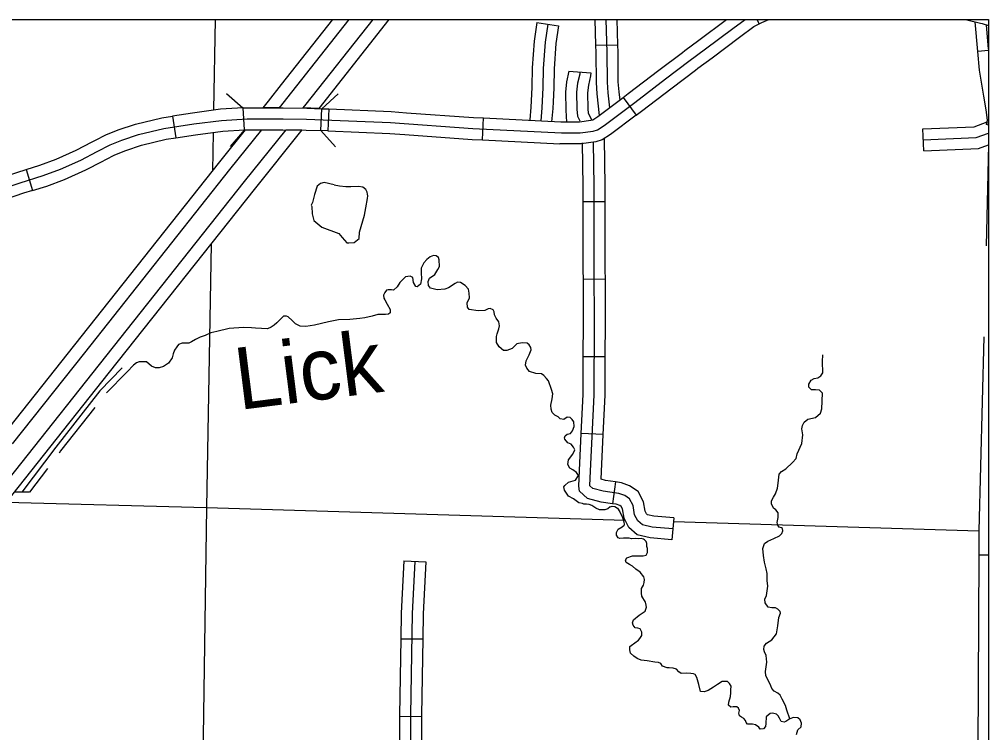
# Model space of a CAD drawing. Extents: x 8749 to 11879, y 13275 to 15339.
# Drawn here: x 10827.5 to 10959.7, y 14359.1 to 14456.3 of the extents above; entities that cross this region are included whole.
import ezdxf

# ---------------------------------------------------------------- set-up
doc = ezdxf.new("R2010")
doc.units = 0
for name, color, linetype in [('Level 19', 7, 'Continuous'), ('Level 31', 7, 'Continuous'), ('Level 32', 7, 'Continuous'), ('Level 35', 7, 'Continuous'), ('Level 38', 7, 'Continuous'), ('Level 4', 7, 'Continuous'), ('Level 43', 7, 'Continuous'), ('Level 45', 7, 'Continuous'), ('Level 5', 7, 'Continuous'), ('R_Draft', 7, 'Continuous')]:
    doc.layers.add(name, color=color, linetype=linetype)

msp = doc.modelspace()

# ---------------------------------------------------------------- linework, layer by layer
at = {"layer": 'Level 19'}
for points in [[(10863.26, 14447.42), (10870.27, 14456.3)], [(10872.44, 14456.3), (10864.6, 14446.37)], [(10866.64, 14444.76), (10875.75, 14456.3)], [(10877.92, 14456.3), (10868.33, 14444.15)], [(10862.95, 14444.27), (10860.77, 14444.26), (10861.5, 14445.17), (10863.26, 14447.42)], [(10864.6, 14446.37), (10862.94, 14444.26)], [(10868.33, 14444.15), (10866.22, 14444.23), (10866.64, 14444.76)], [(10854.85, 14436.88), (10858.35, 14441.25), (10860.54, 14441.26)], [(10860.54, 14441.26), (10856.18, 14435.82)], [(10858.21, 14434.19), (10863.87, 14441.26), (10866.02, 14441.23)], [(10866.02, 14441.23), (10859.54, 14433.13)], [(10835.05, 14411.92), (10854.85, 14436.88)], [(10856.18, 14435.82), (10836.38, 14410.86)], [(10838.41, 14409.25), (10858.21, 14434.19)], [(10859.54, 14433.13), (10839.74, 14408.19)], [(10825.19, 14399.49), (10835.05, 14411.92)], [(10836.38, 14410.86), (10826.52, 14398.43)], [(10828.55, 14396.81), (10838.41, 14409.25)], [(10839.74, 14408.19), (10829.88, 14395.75)], [(10814.02, 14378.49), (10828.55, 14396.81)], [(10829.88, 14395.75), (10815.35, 14377.43)]]:
    msp.add_lwpolyline(points, dxfattribs=at)
at = {"layer": 'Level 31'}
for p, q in [((10928.09, 14456.3), (10928.41, 14455.68)), ((10909.85, 14445.65), (10911.66, 14443.25)), ((10868.75, 14444.13), (10868.75, 14444.13)), ((10869.71, 14444.09), (10869.59, 14441.09)), ((10848.38, 14443.12), (10848.83, 14440.16)), ((10890.66, 14439.86), (10890.8, 14442.86)), ((10890.8, 14442.86), (10890.8, 14442.86)), ((10828.42, 14435.85), (10829.31, 14432.98))]:
    msp.add_line(p, q, dxfattribs=at)
for points in [[(10918.27, 14452.04), (10920.2, 14453.48), (10923.94, 14456.29), (10923.96, 14456.3)], [(10920.06, 14449.63), (10922, 14451.08), (10925.72, 14453.87), (10927.71, 14455.31), (10928.41, 14455.68)], [(10928.41, 14455.68), (10928.77, 14455.86), (10929.75, 14456.3)], [(10956.56, 14456.3), (10958.62, 14455.78)], [(10958.62, 14455.78), (10958.84, 14455.72), (10959.72, 14455.46)], [(10909.85, 14445.65), (10910.55, 14446.18), (10914.73, 14449.38), (10917.94, 14451.79), (10918.27, 14452.04)], [(10911.66, 14443.25), (10912.37, 14443.79), (10916.54, 14446.99), (10919.73, 14449.39), (10920.06, 14449.63)], [(10901.35, 14442.35), (10901.47, 14442.34), (10903.92, 14442.35), (10905.47, 14442.55), (10905.72, 14442.62), (10906.42, 14443.07), (10909.85, 14445.65)], [(10858.01, 14444.23), (10854.94, 14444.04), (10851.1, 14443.54), (10848.38, 14443.12)], [(10858.01, 14444.23), (10859.09, 14444.26)], [(10858.2, 14441.24), (10858.01, 14444.23)], [(10859.09, 14444.26), (10860.86, 14444.26), (10863.48, 14444.26), (10866.71, 14444.22), (10868.75, 14444.13)], [(10868.6, 14441.14), (10868.75, 14444.13)], [(10868.75, 14444.13), (10869.71, 14444.09)], [(10869.71, 14444.09), (10878.21, 14443.73), (10880.3, 14443.58)], [(10837.87, 14439.84), (10839.27, 14440.57), (10840.98, 14441.24), (10843.34, 14442.03), (10846.93, 14442.9), (10848.38, 14443.12)], [(10880.3, 14443.58), (10889.45, 14442.93), (10890.8, 14442.86)], [(10890.8, 14442.86), (10901.35, 14442.35)], [(10911.66, 14443.25), (10908.13, 14440.59), (10906.99, 14439.88), (10906.12, 14439.6), (10904.12, 14439.35), (10901.4, 14439.34), (10901.21, 14439.35)], [(10848.83, 14440.16), (10851.52, 14440.57), (10855.23, 14441.05), (10858.2, 14441.24)], [(10858.2, 14441.24), (10858.6, 14441.26), (10859.09, 14441.26)], [(10859.09, 14441.26), (10860.86, 14441.26), (10863.46, 14441.26), (10866.62, 14441.22), (10868.6, 14441.14)], [(10869.59, 14441.09), (10868.6, 14441.14)], [(10869.59, 14441.09), (10878.04, 14440.73), (10880.09, 14440.59)], [(10828.42, 14435.85), (10830.27, 14436.42), (10832.53, 14437.26), (10835.25, 14438.47), (10837.42, 14439.6), (10837.87, 14439.84)], [(10839.27, 14437.18), (10840.52, 14437.84), (10842, 14438.42), (10844.17, 14439.14), (10847.51, 14439.96), (10848.83, 14440.16)], [(10880.09, 14440.59), (10889.27, 14439.93), (10890.66, 14439.86)], [(10890.66, 14439.86), (10901.21, 14439.35)], [(10829.31, 14432.98), (10831.24, 14433.58), (10833.67, 14434.48), (10836.55, 14435.77), (10838.81, 14436.94), (10839.27, 14437.18)], [(10818.38, 14432.76), (10822.41, 14433.86), (10827.14, 14435.45), (10828.42, 14435.85)], [(10829.31, 14432.98), (10828.07, 14432.6), (10823.29, 14430.99), (10819.17, 14429.86)], [(10881.44, 14382.4), (10881.09, 14375.29), (10880.86, 14361.44), (10880.91, 14354.46), (10880.91, 14345.65)]]:
    msp.add_lwpolyline(points, dxfattribs=at)
at = {"layer": 'Level 32'}
for p, q in [((10906.1, 14452.79), (10909.09, 14452.85)), ((10959.72, 14452.04), (10958.24, 14451.91)), ((10902.47, 14449.24), (10905.45, 14449.02)), ((10950.87, 14438.38), (10950.74, 14441.37)), ((10959.72, 14441.88), (10959.44, 14441.95)), ((10907.39, 14431.44), (10904.39, 14431.42)), ((10907.44, 14420.88), (10904.44, 14420.86)), ((10907.43, 14410.3), (10904.43, 14410.32)), ((10907.13, 14399.69), (10904.14, 14399.83)), ((10908.84, 14393.24), (10908.4, 14390.27)), ((10916.76, 14388.35), (10916.52, 14385.36)), ((10879.94, 14382.48), (10882.94, 14382.33)), ((10879.53, 14371.87), (10882.53, 14371.83)), ((10879.37, 14361.28), (10882.36, 14361.3))]:
    msp.add_line(p, q, dxfattribs=at)
for points in [[(10906.02, 14456.3), (10906.1, 14452.79)], [(10906.35, 14441.25), (10907.27, 14441.83), (10911.46, 14444.99), (10915.64, 14448.19), (10918.84, 14450.59), (10921.1, 14452.28), (10924.83, 14455.08), (10926.52, 14456.3)], [(10907.52, 14456.3), (10907.62, 14451.81), (10907.66, 14447.74), (10907.77, 14446.3), (10908, 14444.26)], [(10909.02, 14456.3), (10909.09, 14452.85)], [(10958.24, 14451.91), (10957.89, 14455.96)], [(10959.72, 14452.25), (10959.43, 14455.54)], [(10906.1, 14452.79), (10906.12, 14451.78), (10906.16, 14447.68), (10906.28, 14446.16), (10906.61, 14443.21)], [(10909.09, 14452.85), (10909.12, 14451.84), (10909.16, 14447.81), (10909.27, 14446.44), (10909.39, 14445.31)], [(10959.44, 14441.95), (10959.58, 14442.57), (10959.4, 14443.95), (10959.05, 14445.84), (10958.46, 14449.38), (10958.24, 14451.91)], [(10902.47, 14449.24), (10902.13, 14447.79), (10901.98, 14446.38), (10902.03, 14443.93), (10902.15, 14442.28)], [(10903.96, 14449.13), (10903.94, 14448.84), (10903.65, 14447.6), (10903.51, 14446.37), (10903.56, 14444.06), (10903.62, 14443.13), (10903.96, 14442.45)], [(10905.45, 14449.02), (10905.42, 14448.61), (10905.13, 14447.35), (10905.02, 14446.31), (10905.06, 14444.13), (10905.1, 14443.53), (10905.58, 14442.58)], [(10811.93, 14429.44), (10822.85, 14432.42), (10827.6, 14434.02), (10830.76, 14435), (10833.1, 14435.87), (10835.9, 14437.12), (10838.12, 14438.27), (10839.89, 14439.21), (10841.49, 14439.83), (10843.76, 14440.59), (10847.22, 14441.43), (10851.31, 14442.05), (10855.08, 14442.54), (10858.55, 14442.76), (10860.86, 14442.76), (10863.47, 14442.76), (10866.66, 14442.72), (10878.12, 14442.23), (10889.36, 14441.43), (10901.43, 14440.84), (10904.02, 14440.85), (10905.79, 14441.07), (10906.35, 14441.25)], [(10950.74, 14441.37), (10957.74, 14441.67), (10959.53, 14442.34), (10959.44, 14441.95)], [(10907.39, 14431.44), (10907.39, 14433.6), (10907.31, 14440.08)], [(10950.8, 14439.87), (10958.04, 14440.19)], [(10958.04, 14440.19), (10959.72, 14440.81)], [(10904.39, 14431.42), (10904.39, 14433.58), (10904.31, 14439.49)], [(10905.32, 14392.73), (10905.31, 14392.77), (10905.4, 14394.73), (10905.89, 14405.12), (10905.97, 14414.96), (10905.93, 14422.17), (10905.89, 14433.59), (10905.81, 14439.51)], [(10950.87, 14438.38), (10958.34, 14438.7), (10959.72, 14439.21)], [(10904.44, 14420.86), (10904.43, 14422.16), (10904.39, 14431.42)], [(10907.44, 14420.88), (10907.43, 14422.17), (10907.39, 14431.44)], [(10904.43, 14410.32), (10904.47, 14414.97), (10904.44, 14420.86)], [(10907.43, 14410.3), (10907.47, 14414.96), (10907.44, 14420.88)], [(10904.14, 14399.83), (10904.39, 14405.16), (10904.43, 14410.32)], [(10907.13, 14399.69), (10907.39, 14405.07), (10907.43, 14410.3)], [(10908.4, 14390.27), (10906.85, 14390.5), (10904.98, 14390.98), (10903.92, 14391.99), (10903.8, 14392.68), (10903.9, 14394.8), (10904.14, 14399.83)], [(10908.84, 14393.24), (10907.44, 14393.44), (10906.85, 14393.6), (10906.9, 14394.66), (10907.13, 14399.69)], [(10916.64, 14386.86), (10913.81, 14387.09), (10912.48, 14387.41), (10911.85, 14387.95), (10911.43, 14388.78), (10911.21, 14390.05), (10910.75, 14390.92), (10910.07, 14391.38), (10909.29, 14391.65), (10907.15, 14391.97), (10905.73, 14392.34), (10905.32, 14392.73)], [(10916.76, 14388.35), (10914.05, 14388.57), (10913.19, 14388.78), (10913.05, 14388.89), (10912.87, 14389.25), (10912.64, 14390.55), (10911.9, 14391.96), (10910.74, 14392.73), (10909.65, 14393.12), (10908.84, 14393.24)], [(10916.52, 14385.36), (10913.57, 14385.6), (10911.78, 14386.03), (10910.64, 14387.01), (10910, 14388.3), (10909.77, 14389.56), (10909.6, 14389.89), (10909.39, 14390.03), (10908.93, 14390.19), (10908.4, 14390.27)], [(10879.94, 14382.48), (10879.59, 14375.34), (10879.53, 14371.87)], [(10882.94, 14382.33), (10882.59, 14375.24), (10882.53, 14371.83)], [(10879.53, 14371.87), (10879.36, 14361.44), (10879.37, 14361.28)], [(10882.53, 14371.83), (10882.36, 14361.43), (10882.36, 14361.3)], [(10879.37, 14361.28), (10879.41, 14354.45), (10879.41, 14350.73)], [(10882.36, 14361.3), (10882.41, 14354.46), (10882.41, 14350.73)]]:
    msp.add_lwpolyline(points, dxfattribs=at)
at = {"layer": 'Level 35'}
for points in [[(10870.42, 14433.76), (10869.06, 14434.06), (10868.58, 14433.91), (10868.13, 14433.56), (10867.78, 14432.45), (10867.48, 14431.34), (10867.3, 14430.99), (10867.38, 14430.79), (10867.45, 14429.8), (10867.65, 14428.89), (10868.74, 14427.96), (10871.08, 14427.1), (10871.51, 14426.55), (10872.19, 14425.84), (10872.46, 14425.84), (10873.15, 14425.89), (10873.85, 14426.42), (10873.88, 14427.31), (10874.56, 14429.6), (10874.76, 14430.61), (10874.98, 14431.9), (10875.03, 14432.25), (10874.98, 14432.48), (10874.96, 14432.75), (10874.78, 14433.11), (10874.35, 14433.41), (10873.78, 14433.51), (10872.72, 14433.46), (10872.04, 14433.46), (10871.18, 14433.58), (10870.42, 14433.71)], [(10886.93, 14420.28), (10886.05, 14419.72), (10885.54, 14419.52), (10884.49, 14419.42), (10883.6, 14419.64), (10883.33, 14420.02), (10883.25, 14420.55), (10883.45, 14421.01), (10884.18, 14421.51), (10884.59, 14422.19), (10884.81, 14422.62), (10884.76, 14423.5), (10884.66, 14423.86), (10884.36, 14424.06), (10884.01, 14424.11), (10883.53, 14423.93), (10883.08, 14423.58), (10882.65, 14423.12)], [(10882.65, 14423.12), (10882.32, 14422.37), (10882.3, 14421.76), (10882.37, 14420.93), (10882.2, 14420.2), (10881.77, 14419.85), (10881.57, 14419.9), (10881.26, 14420.43), (10881.16, 14421.11), (10880.8, 14421.29), (10880.18, 14421.21), (10879.4, 14420.45), (10879.02, 14419.85), (10878.52, 14419.39), (10878.27, 14419.42), (10877.81, 14419.42), (10877.56, 14419.37), (10877.33, 14419.09), (10877.18, 14418.69), (10877.23, 14418.31), (10877.36, 14418.08), (10877.66, 14417.5)], [(10890.98, 14416.62), (10890.08, 14416.57), (10888.87, 14416.74), (10888.64, 14417.07), (10888.57, 14417.65), (10888.9, 14418.33), (10888.85, 14418.99), (10888.77, 14419.52), (10888.32, 14420.02), (10887.69, 14420.45), (10887.26, 14420.48), (10886.93, 14420.28)], [(10877.66, 14417.5), (10878.06, 14416.74), (10878.06, 14416.29), (10877.86, 14416.11), (10877.46, 14416.06), (10876.4, 14416.09), (10875.62, 14415.84), (10874.64, 14415.61), (10873.96, 14415.53), (10872.57, 14415.41), (10871.03, 14415.36), (10869.67, 14415.08), (10867.76, 14414.63)], [(10892.59, 14413.08), (10892.67, 14413.45), (10892.92, 14414.13), (10893, 14414.51), (10892.92, 14415.06), (10892.52, 14415.56), (10892.32, 14416.02), (10892.27, 14416.42), (10892.12, 14416.72), (10891.74, 14416.88), (10891.44, 14416.85), (10890.98, 14416.62)], [(10867.76, 14414.63), (10866.58, 14414.45), (10865.82, 14414.5), (10865.16, 14414.8), (10864.69, 14415.26), (10864.16, 14415.74), (10863.93, 14415.86), (10863.55, 14415.84), (10863.2, 14415.53), (10862.62, 14414.93), (10862.24, 14414.63), (10861.84, 14414.32)], [(10853.6, 14413.57), (10852.85, 14413.22), (10852.17, 14412.97), (10851.52, 14412.64), (10850.99, 14412.34), (10850.63, 14412.16), (10850.23, 14412.14), (10849.7, 14412.16), (10849.2, 14411.96), (10848.97, 14411.66), (10848.64, 14411.21), (10848.47, 14410.7), (10848.34, 14410.17), (10847.86, 14409.44), (10847.16, 14408.99), (10846.55, 14408.79), (10846.07, 14408.79), (10845.52, 14409.01)], [(10861.84, 14414.32), (10861.34, 14414.12), (10860.51, 14414.17), (10859.73, 14414.22), (10859.17, 14414.27), (10858.06, 14414.3), (10856.12, 14414.17), (10854.44, 14413.77), (10853.6, 14413.57)], [(10897.96, 14408.01), (10897.1, 14408.31), (10896.73, 14408.74), (10896.55, 14409.17), (10896.63, 14409.77), (10897.05, 14410.58), (10897.31, 14411.23), (10897.28, 14411.56), (10897.05, 14411.94), (10896.78, 14412.17), (10896.07, 14412.22), (10895.34, 14412.09), (10894.74, 14411.44), (10893.98, 14411.18), (10893.53, 14411.18), (10892.95, 14411.64), (10892.59, 14412.27), (10892.59, 14413.08)], [(10845.52, 14409.01), (10844.84, 14409.61), (10844.23, 14409.61), (10843.83, 14409.63), (10843.47, 14409.5), (10843.07, 14409.16), (10842.19, 14408.25), (10842.14, 14408.2)], [(10937.06, 14405.35), (10936.63, 14405.74), (10936.12, 14405.82), (10935.57, 14405.82), (10935.19, 14406.17), (10935.19, 14406.58), (10935.52, 14407.11), (10935.9, 14407.36), (10936.4, 14407.43), (10936.83, 14407.69), (10937.11, 14408.11), (10937.06, 14409.68), (10937.09, 14410.55)], [(10900, 14403.71), (10900.2, 14404.58), (10900.25, 14405.24), (10900.1, 14405.84), (10899.7, 14407.03), (10899.42, 14407.36), (10899.02, 14407.76), (10898.74, 14407.96), (10897.96, 14408.01)], [(10936.1, 14402.03), (10936.78, 14402.62), (10936.96, 14403.2), (10937.06, 14405.35)], [(10901.76, 14392.57), (10901.89, 14392.77), (10902.39, 14393.2), (10903.35, 14393.47), (10903.75, 14394.13), (10903.48, 14394.51), (10903, 14394.91), (10902.57, 14395.14), (10902.32, 14395.62), (10902.42, 14396.25), (10903.02, 14397.05), (10903.25, 14397.63), (10903.1, 14397.99), (10902.75, 14398.37), (10902.32, 14398.57), (10901.89, 14399.07), (10901.86, 14399.27), (10901.96, 14399.55), (10902.24, 14399.75), (10902.7, 14399.83), (10902.95, 14400.21), (10903.17, 14400.79), (10903.12, 14401.44), (10902.92, 14401.77), (10902.62, 14402.02), (10902.22, 14402.05), (10901.76, 14401.74), (10901.26, 14401.85), (10900.98, 14402.12), (10900.55, 14402.35), (10900.18, 14402.73), (10900.05, 14403.16), (10900, 14403.71)], [(10931.16, 14394.28), (10931.46, 14394.67), (10932.04, 14395.05), (10932.97, 14395.88), (10933.48, 14396.46), (10933.58, 14397.07), (10934.23, 14398.48), (10934.39, 14399.66), (10934.26, 14400.5), (10934.31, 14400.93), (10934.56, 14401.4), (10935.04, 14401.78), (10936.1, 14402.03)], [(10931.46, 14386.99), (10931.14, 14387.09), (10930.98, 14387.34), (10930.86, 14387.7), (10931.01, 14388.4), (10931.03, 14389.01), (10930.68, 14389.46), (10930.38, 14389.66), (10930.1, 14390.26), (10930.1, 14390.67), (10930.38, 14391.15), (10930.66, 14391.6), (10930.91, 14392.39), (10931.03, 14393.07), (10931.16, 14394.28)], [(10908.1, 14389.86), (10907.78, 14389.57), (10907.38, 14389.42), (10907.1, 14389.42), (10906.65, 14389.45), (10906.12, 14389.67), (10905.59, 14390.05), (10905.21, 14390.15), (10904.86, 14390.23), (10904.51, 14390.23), (10904.31, 14390.28), (10903.8, 14390.38), (10903.8, 14390.38), (10903.07, 14390.93), (10902.42, 14391.31), (10902.12, 14391.72), (10901.84, 14392.14), (10901.76, 14392.57)], [(10828.9, 14391.83), (10826.79, 14391.85)], [(10908.1, 14389.86), (10908.36, 14389.95), (10908.71, 14389.9), (10909.08, 14389.66), (10909.41, 14389.17), (10909.79, 14388.39), (10909.97, 14387.8), (10910, 14387.46), (10909.94, 14387.28), (10909.79, 14387.12)], [(10910.69, 14385.58), (10909.9, 14385.57), (10909.4, 14385.54), (10909.17, 14385.62), (10908.97, 14385.97), (10908.94, 14386.35), (10909.2, 14386.8), (10909.75, 14387.11), (10909.79, 14387.12)], [(10928.94, 14384.19), (10929.15, 14384.85), (10929.6, 14385.17), (10930.4, 14385.55), (10931.21, 14385.91), (10931.51, 14386.23), (10931.64, 14386.59), (10931.59, 14386.89), (10931.46, 14386.99)], [(10913.2, 14384.19), (10913.08, 14384.42), (10913.09, 14384.85), (10912.99, 14385.13), (10912.79, 14385.35), (10912.65, 14385.45), (10912.33, 14385.52), (10911.9, 14385.5), (10911.53, 14385.52), (10910.98, 14385.5), (10910.69, 14385.58)], [(10912.9, 14376.83), (10912.42, 14377.69), (10912.35, 14378.06), (10912.37, 14378.7), (10912.62, 14379.17), (10912.75, 14379.53), (10912.77, 14379.96), (10912.67, 14380.31), (10912.19, 14380.96), (10911.61, 14381.37), (10911.16, 14381.75), (10910.71, 14382), (10910.28, 14382.28), (10910.18, 14382.58), (10910.38, 14382.91), (10911.16, 14383.18), (10911.77, 14383.18), (10912.6, 14383.16), (10913, 14383.26), (10913.2, 14383.64), (10913.2, 14384.19)], [(10929.47, 14368.66), (10929.37, 14369.6), (10929.15, 14370.06), (10929.04, 14370.41), (10929.09, 14370.84), (10929.4, 14371.27), (10930.13, 14371.72), (10930.76, 14372.55), (10930.96, 14373.61), (10931.11, 14374.75), (10931.34, 14375.33), (10931.29, 14375.58), (10930.98, 14375.91), (10930.66, 14376.09), (10930.13, 14376.06), (10929.65, 14376.16), (10929.22, 14376.74), (10929.2, 14377.25), (10929.42, 14377.77), (10929.6, 14379.01), (10929.52, 14379.79), (10929.5, 14380.78), (10929.35, 14381.41), (10929.15, 14382.3), (10928.99, 14383.21), (10928.94, 14384.19)], [(10910.88, 14369.88), (10910.76, 14370.35), (10910.78, 14370.8), (10910.96, 14370.95), (10911.97, 14371.66), (10912.14, 14371.89), (10912.4, 14372.31), (10912.42, 14372.74), (10912.17, 14373.22), (10911.87, 14373.3), (10911.51, 14373.35), (10911.21, 14373.7), (10911.14, 14374.03), (10911.26, 14374.46), (10912.04, 14375.09), (10912.87, 14375.64), (10913.05, 14376.15), (10912.97, 14376.68), (10912.9, 14376.83)], [(10920.42, 14364.66), (10920.2, 14365.62), (10919.92, 14366.6), (10919.7, 14367), (10919.45, 14367.1), (10919.09, 14367.13), (10918.54, 14367.16), (10917.78, 14367.13), (10917.48, 14367.36), (10917.15, 14367.71), (10916.7, 14367.86), (10916.14, 14367.89), (10915.87, 14367.91), (10915.24, 14368.11), (10915.01, 14368.49), (10914.69, 14368.64), (10914.2, 14368.69), (10913.12, 14368.87), (10912.32, 14368.96), (10911.76, 14369.17), (10911.31, 14369.48), (10910.88, 14369.88)], [(10932.59, 14360.96), (10932.17, 14362.11), (10932.02, 14362.76), (10931.56, 14363.64), (10931.29, 14364.17), (10930.96, 14364.45), (10930.48, 14364.7), (10930.15, 14365.08), (10930, 14365.44), (10929.72, 14366.02), (10929.32, 14366.8), (10929.27, 14367.38), (10929.47, 14368.66)], [(10927.5, 14360.23), (10927, 14360.2), (10926.82, 14360.23), (10926.65, 14360.43), (10926.55, 14360.73), (10926.34, 14360.98), (10925.99, 14361.16), (10925.74, 14361.36), (10925.64, 14361.71), (10925.74, 14362.09), (10925.61, 14362.42), (10925.39, 14362.6), (10924.88, 14362.57), (10924.55, 14362.55), (10924.25, 14362.82), (10924.3, 14363.2), (10924.5, 14363.98), (10924.53, 14364.51), (10924.53, 14364.89), (10924.58, 14365.39), (10924.38, 14365.75), (10924.1, 14366.05), (10923.35, 14366.05), (10922.74, 14365.62), (10922.21, 14365.27), (10921.46, 14364.79), (10920.9, 14364.64), (10920.42, 14364.66)], [(10933.5, 14358.81), (10933.7, 14359.44), (10934.13, 14359.87), (10934.2, 14360.35), (10934.03, 14360.81), (10933.7, 14361.06), (10933.12, 14361.11), (10932.59, 14360.96), (10932.04, 14360.6), (10931.81, 14360.48), (10931.41, 14360.6), (10931.21, 14361.03), (10931.03, 14361.36), (10930.8, 14361.56), (10930.22, 14361.71), (10929.9, 14361.66), (10929.37, 14361.21), (10929.32, 14360.33), (10929.29, 14359.92), (10928.99, 14359.59), (10928.56, 14359.52), (10928.36, 14359.82), (10927.93, 14360.12), (10927.5, 14360.23)]]:
    msp.add_lwpolyline(points, dxfattribs=at)
at = {"layer": 'Level 38'}
for points in [[(10855.74, 14446.2), (10858, 14444.23)], [(10868.75, 14444.13), (10870.97, 14446.15)], [(10858.21, 14441.24), (10856.24, 14438.97)], [(10870.61, 14438.91), (10868.6, 14441.14)]]:
    msp.add_lwpolyline(points, dxfattribs=at)
at = {"layer": 'Level 4'}
for points in [[(10959.72, 14439.21), (10959.37, 14425.42)], [(10959.06, 14413.02), (10958.4, 14386.56), (10958.38, 14383.3), (10958.02, 14312.63)]]:
    msp.add_lwpolyline(points, dxfattribs=at)
at = {"layer": 'Level 43'}
for points in [[(10841.54, 14408.79), (10838.46, 14405.65), (10832.47, 14397.98), (10827.85, 14391.84)], [(10842.14, 14408.2), (10839.37, 14405.37)], [(10837.77, 14403.4), (10833.13, 14397.47), (10832.91, 14397.17)], [(10831.32, 14395.06), (10828.9, 14391.83)]]:
    msp.add_lwpolyline(points, dxfattribs=at)
at = {"layer": 'Level 45'}
msp.add_line((10898.08, 14455.87), (10901.05, 14455.44), dxfattribs=at)
for points in [[(10898.08, 14455.87), (10897.72, 14453.35), (10897.44, 14449.68), (10897.4, 14447.05), (10897.33, 14445.19)], [(10899.57, 14455.66), (10899.21, 14453.19), (10898.94, 14449.61), (10898.9, 14447.01), (10898.79, 14444.25), (10898.62, 14442.46)], [(10901.05, 14455.44), (10900.7, 14453.03), (10900.44, 14449.54), (10900.4, 14446.96), (10900.32, 14445.07)], [(10897.33, 14445.19), (10897.29, 14444.35), (10897.13, 14442.6)], [(10900.32, 14445.07), (10900.29, 14444.15), (10900.11, 14442.32)]]:
    msp.add_lwpolyline(points, dxfattribs=at)
at = {"layer": 'Level 5'}
for points in [[(10854.2, 14456.3), (10853.98, 14443.91)], [(10853.92, 14440.88), (10853.83, 14435.59)], [(10853.65, 14425.72), (10853.02, 14389.78)], [(10825.7, 14390.48), (10853.02, 14389.78)], [(10853.02, 14389.78), (10852.21, 14333.56)], [(10853.02, 14389.78), (10910.13, 14388.03)], [(10916.72, 14387.83), (10958.4, 14386.56)], [(10958.38, 14383.3), (10959.72, 14383.3)]]:
    msp.add_lwpolyline(points, dxfattribs=at)
at = {"layer": 'R_Draft'}
msp.add_lwpolyline([(9678.09, 14456.3), (10959.72, 14456.3), (10959.72, 13439.87), (9678.09, 13439.87)], close=True, dxfattribs=at)

# ---------------------------------------------------------------- texts
at = {"layer": 'Level 35'}
msp.add_text('Lick', height=8.448, rotation=7.2063, dxfattribs=at).set_placement((10857.45, 14403.04))

doc.saveas('drawing.dxf')
